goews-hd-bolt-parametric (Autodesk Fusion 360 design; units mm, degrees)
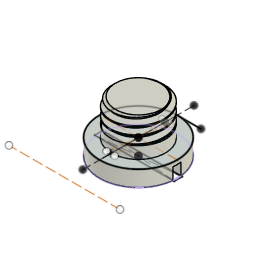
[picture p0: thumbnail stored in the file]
parameter "Boltlength" = 9
cylinder_primitive "CylinderPrimitive1" Height 9 (= "Boltlength") Diameter 14 bodies "Bolt"
thread "Thread1" ThreadOffset 3 ThreadLength 5.9 (= "Boltlength - 3.1 mm")
chamfer "Chamfer1" distance 1
sketch "Head" plane through (0, 0, 0) normal (0, 0, -1) x axis (1, 0, 0)
  line L1 (0, 9.761) -> (0, -9.761)
  line L2 (1, -7) -> (-1, 7)
  line L3 (-1, -7) -> (1, 7)
  line L4 (-9.761, 0) -> (9.761, 0)
  line L5 (0, -6.761) -> (0, 6.761)
  line L6 (0, 14) -> (0, -14)
  line L7 (-14.605, 18) -> (13.3677, 18)
  line L8 (0, 9.761) -> (0, -9.761)
  line L9 (6, -9.761) -> (0, -9.761)
  circle C1 centre (0, 0) radius 6.761
  circle C2 centre (0, 0) radius 9.761
  point P5 (0, 9.761)
  point P4 (0, -9.761)
  point P10 (0, 0)
  point P2 (0, 0)
  point P12 (-9.761, 0)
  point P11 (9.761, 0)
  point P14 (0, -6.761)
  point P15 (0, 0)
  point P18 (0, 0)
  point P22 (0, 9.761)
  point P23 (0, 0)
  point P8 (1, -7)
  point P9 (-1, -7)
  point P7 (1, 7)
  point P13 (0, 6.761)
  point P16 (0, -14)
  point P17 (0, 14)
  point P21 (0, -9.761)
  point P24 (6, -9.761)
  coincident C2 P5
  vertical L1
  coincident C2 P4
  coincident L2 P10
  coincident L3 P10
  coincident P2 P10
  coincident C2 P12
  coincident C2 P11
  coincident L1 P14
  coincident C1 P14
  coincident P10 P15
  midpoint L5 P15
  parallel L1 L6
  coincident P15 P18
  midpoint L6 P18
  coincident P5 P22
  parallel L1 L8
  coincident P18 P23
  midpoint L8 P23
  perpendicular L1 L9
  dimension "d7" = 3
  dimension "d9" distance P8 P9 = 2
  dimension "d10" distance P7 P8 = 14
  dimension "d25" distance P13 P14 = 13.522
  dimension "d27" distance P16 P17 = 28
  dimension "d28" distance P10 L7 = 18
  dimension "d33" distance P21 P24 = 6
extrude "Extrude1" add sketch "Head" profile of C1 C2 along normal blind 4
sketch "Sketch4" plane through (0, 0, -4) normal (0, 0, -1) x axis (1, 0, 0)
  line L1 (10, 1) -> (-10, 1)
  line L2 (10, -1) -> (10, 1)
  line L3 (-10, -1) -> (10, -1)
  line L4 (-10, 1) -> (-10, -1)
  line L5 (10, -1) -> (-10, 1)
  line L6 (-10, -1) -> (10, 1)
  circle C1 centre (0, 0) radius 9.761
  point P2 (0, 0)
  point P3 (0, 0)
  point P8 (0, 0)
  point P6 (10, -1)
  point P7 (-10, -1)
  point P5 (10, 1)
  coincident P2 P3
  horizontal L1
  perpendicular L1 L2
  parallel L1 L3
  parallel L2 L4
  coincident L5 P8
  coincident L6 P8
  coincident P2 P8
  dimension "d44" distance P6 P7 = 20
  dimension "d45" distance P5 P6 = 2
component_from_bodies "Body->Comp"
extrude "Extrude1" cut sketch "Sketch4" profile of C1 L1 L3 against normal blind 3
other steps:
base_feature "Base Feature" sketch "Sketch4" bodies "Bolt"
create_component "CreateComponent1" sketch "Sketch4"
place_component sketch "Sketch4"
remove_body "RemoveBody1"
named bodies: "Bolt"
